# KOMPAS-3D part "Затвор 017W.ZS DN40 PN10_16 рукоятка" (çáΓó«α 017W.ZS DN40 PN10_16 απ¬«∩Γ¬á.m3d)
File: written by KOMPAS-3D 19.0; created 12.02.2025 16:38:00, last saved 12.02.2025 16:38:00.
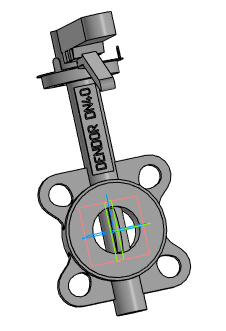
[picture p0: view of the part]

Document properties: Автор: Евгений; Полное имя файла: Затвор 017W.ZS DN40 PN10_16 рукоятка.a3d

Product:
- Part/product: Затвор 017W.ZS DN40 PN10_16 рукоятка
    Масса: 3.54906

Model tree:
1. Операция без истории:1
